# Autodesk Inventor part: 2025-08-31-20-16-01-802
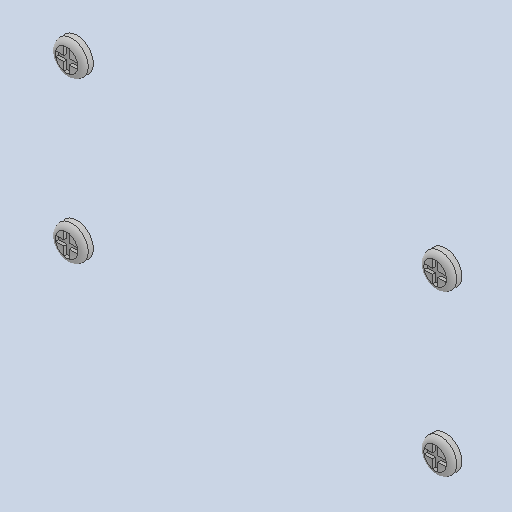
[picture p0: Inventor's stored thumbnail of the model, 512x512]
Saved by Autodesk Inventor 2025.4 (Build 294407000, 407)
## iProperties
Created: 2026-09
Part Number: 2025-08-31-20-16-01-802
Material: Generic
Document SubType Name: Modeling
Designer: AdminForWorker
Density: 1 g/cm^3
Appearance: Default
Title: bolts
Author: AdminForWorker
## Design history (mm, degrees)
feature "Body1"
feature "Body2"
feature "Body3"
feature "Body4"
body "Solid1"
body "Solid2"
body "Solid3"
body "Solid4"
